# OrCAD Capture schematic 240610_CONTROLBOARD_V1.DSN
size A4; title: CONTROL BOARD_HWANG CHAE HWI; rev: V1; note: ECLECTRONIC CAD 2024.06.10
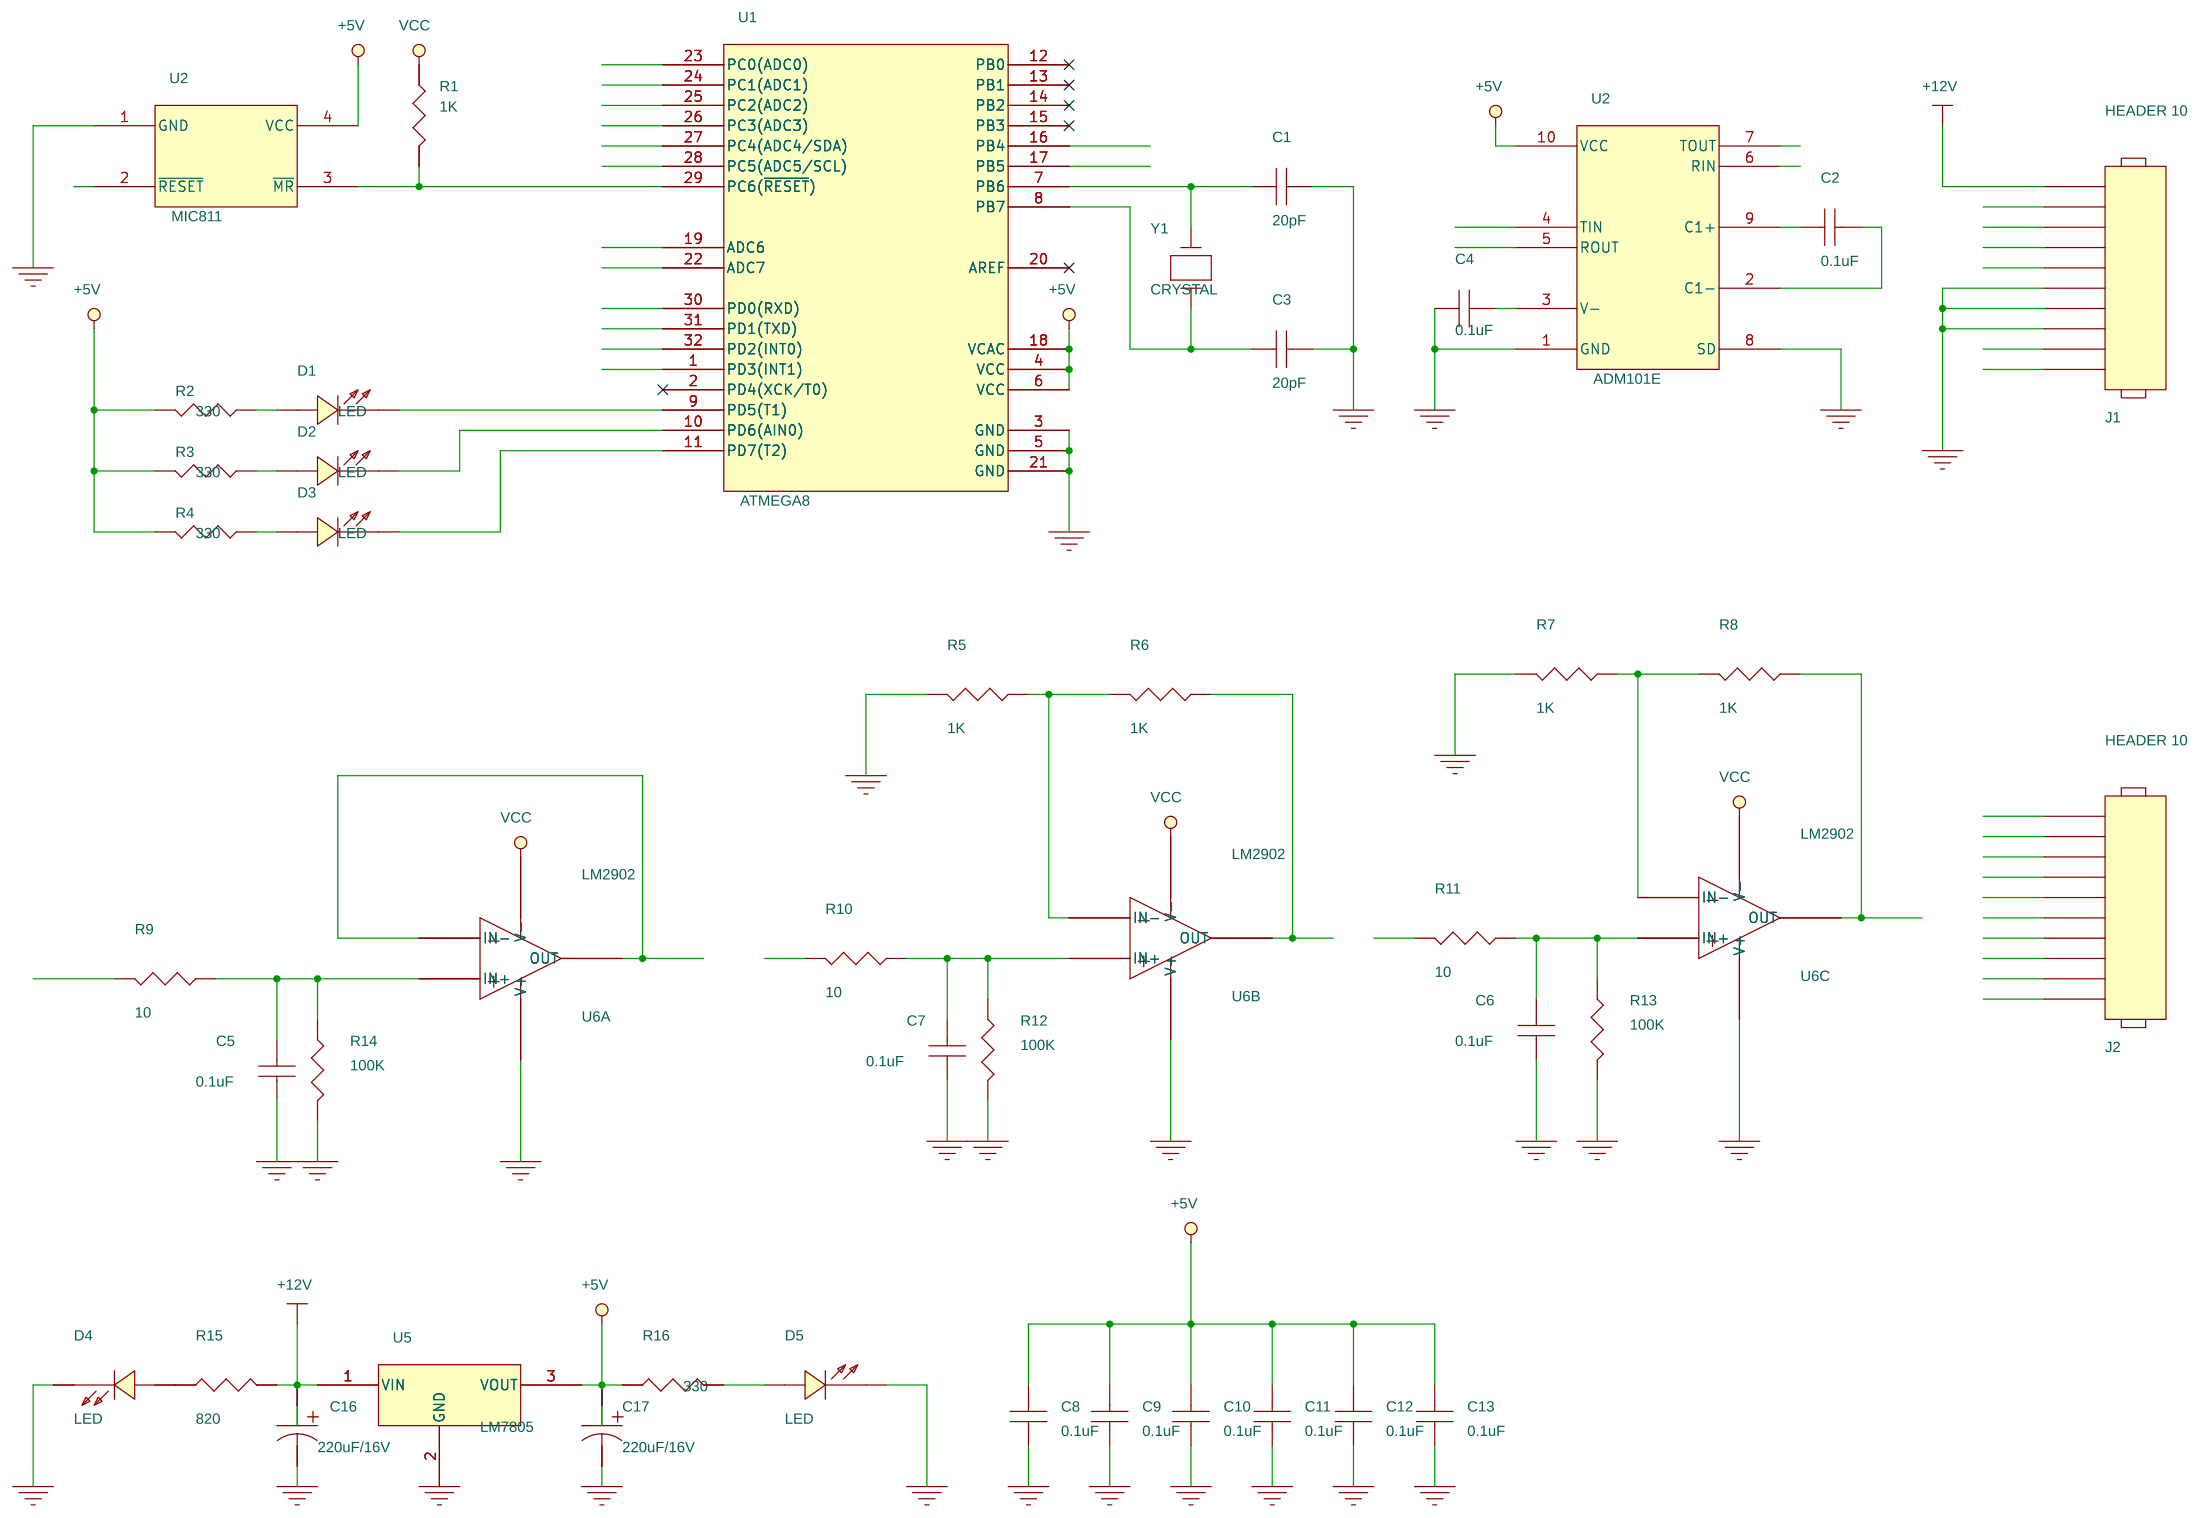
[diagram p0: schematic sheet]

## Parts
C1  20pF
C2  0.1uF
C3  20pF
C4  0.1uF
C5  0.1uF
C6  0.1uF
C7  0.1uF
C8  0.1uF
C9  0.1uF
C10  0.1uF
C11  0.1uF
C12  0.1uF
C13  0.1uF
C16  220uF/16V
C17  220uF/16V
D1  LED
D2  LED
D3  LED
D4  LED
D5  LED
J1  HEADER 10
J2  HEADER 10
R1  1K
R2  330
R3  330
R4  330
R5  1K
R6  1K
R7  1K
R8  1K
R9  10
R10  10
R11  10
R12  100K
R13  100K
R14  100K
R15  820
R16  330
U1  ATMEGA8
U2  MIC811
U5  LM7805
U6  LM2902  (sections A,B,C)
Y1  CRYSTAL

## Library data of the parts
C1-C13 = CAP_NP
C16 C17 = CAP_POL
D1-D5 = LED
J1 J2 = HEADER_10
R1-R16 = R
U1 = ATMEGA8
U2 = MIC811
U5 = LM7805
U6 = LM2902_8
Y1 = CRYSTAL

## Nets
+5V: C8.2 C9.2 C10.2 C11.2 C12.2 C13.2 C17.1 R1.1 R2.2 R3.2 R4.2 R16.1 U1.4(VCC) U1.6(VCC) U1.18(VCAC) U2.4(VCC) U2.10(VCC) U5.3(VOUT) U6.11(V-)
+12V: C16.1 J1.1 R15.2 U5.1(VIN)
GND: C1.2 C3.2 C4.1 C5.1 C6.1 C7.1 C8.1 C9.1 C10.1 C11.1 C12.1 C13.1 C16.2 C17.2 D4.1(CATHODE) D5.1(CATHODE) J1.6 J1.7 J1.8 R5.2 R7.2 R12.2 R13.2 R14.2 U1.3(GND) U1.5(GND) U1.21(GND) U2.1(GND) U2.8(SD) U5.2(GND) U6.4(V+)
N01780: C4.2 R1.2 U1.29(PC6(~{RESET})) U2.3(~{MR})
N01808: D1.1(CATHODE) U1.9(PD5(T1))
N01812: D2.1(CATHODE) U1.10(PD6(AIN0))
N01824: D3.1(CATHODE) U1.11(PD7(T2))
N01847: D1.2(ANODE) R2.1
N01851: D2.2(ANODE) R3.1
N01855: D3.2(ANODE) R4.1
N01909: C2.1 U2.9(C1+)
N01913: C2.2 U2.2(~{RESET})
N02587: C5.2 R9.1 R14.1 U6.3(IN+)
N02643: C7.2 R10.1 R12.1 U6.5(IN+)
N03835: R5.1 R6.2 U6.6(IN-)
N03845: R6.1 U6.7(OUT)
N03897: C6.2 R11.1 R13.1 U6.10(IN+)
N03933: R7.1 R8.2 U6.9(IN-)
N03937: R8.1 U6.8(OUT)
N04045: D5.2(ANODE) R16.2
N05218: U6.1(OUT) U6.2(IN-)
N06547: C1.1 U1.7(PB6) Y1.2
N07241: C3.1 U1.8(PB7) Y1.1
N14895: D4.2(ANODE) R15.1

Not connected (* = marked no-connect by the designer): J1 2 3 4 5 9 10; J2 1 2 3 4 5 6 7 8 9 10; R9 2; R10 2; R11 2; U1 1(PD3(INT1)) 2(PD4(XCK/T0))* 12(PB0)* 13(PB1)* 14(PB2)* 15(PB3)* 16(PB4) 17(PB5) 19(ADC6) 20(AREF)* 22(ADC7) 23(PC0(ADC0)) 24(PC1(ADC1)) 25(PC2(ADC2)) 26(PC3(ADC3)) 27(PC4(ADC4/SDA)) 28(PC5(ADC5/SCL)) 30(PD0(RXD)) 31(PD1(TXD)) 32(PD2(INT0)); U2 5(ROUT) 6(RIN) 7(TOUT)
